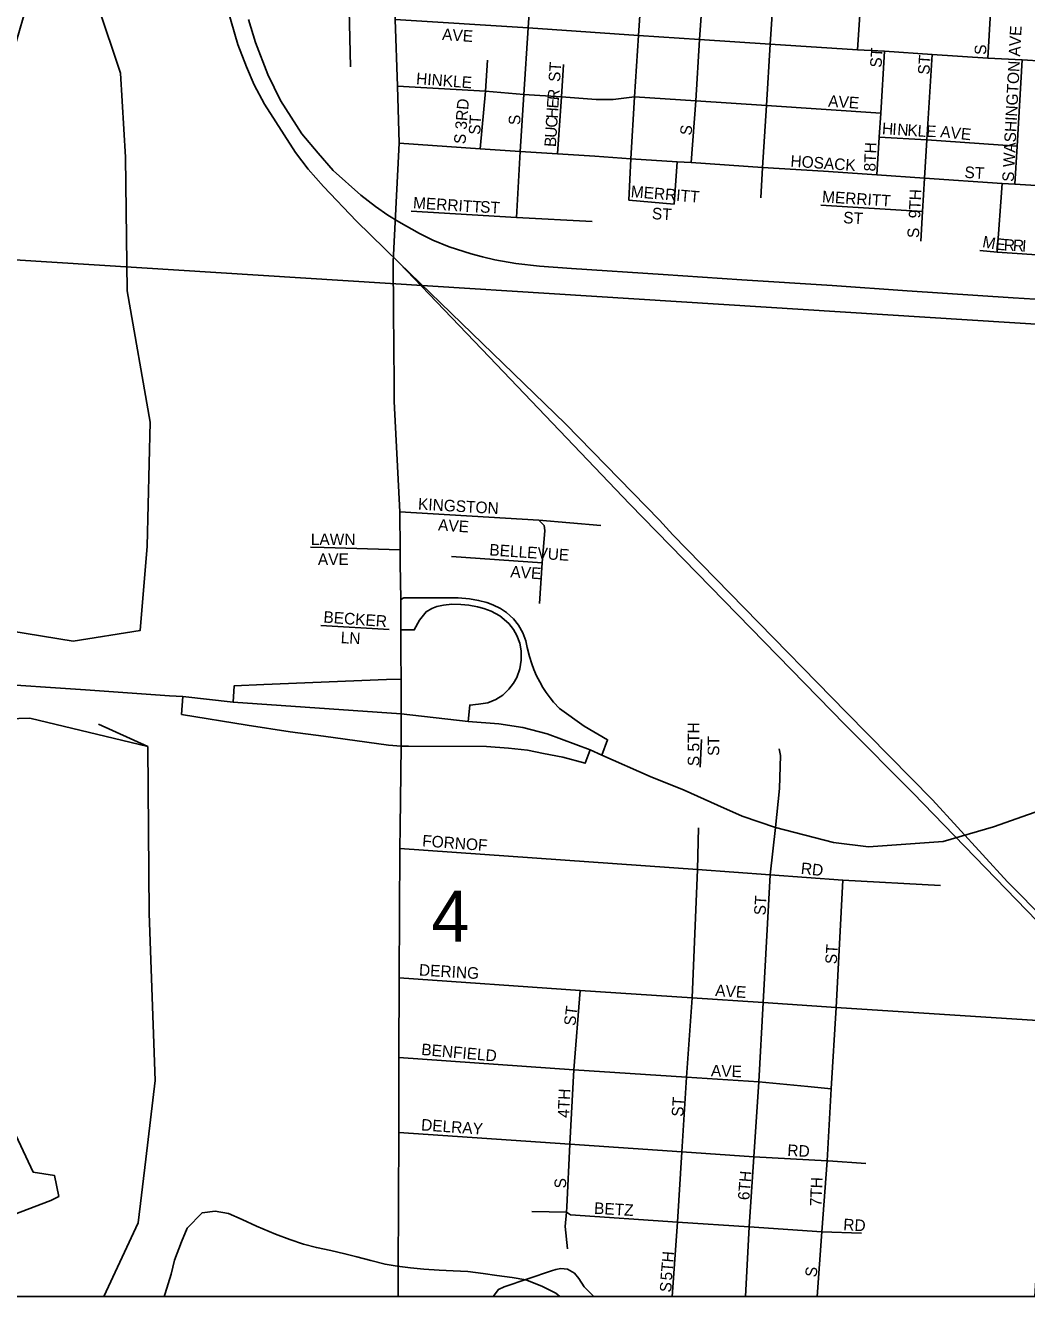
# Model space of a CAD drawing. Extents: x 0 to 34, y -6.2 to 22.
# Drawn here: x 6.622 to 7.442, y 14.39 to 15.431 of the extents above; entities that cross this region are included whole.
import ezdxf

# ---------------------------------------------------------------- set-up
doc = ezdxf.new("R2010")
doc.units = 0
for name, color, linetype in [('GM_X_City_Street', 7, 'Continuous'), ('GM_X_City_Street_Text', 7, 'Continuous'), ('GM_X_Corporation', 7, 'Continuous'), ('GM_X_Interchange_Ramps', 7, 'Continuous'), ('GM_X_Minor_Lake', 7, 'Continuous'), ('GM_X_Minor_River', 7, 'Continuous'), ('GM_X_Rail_Line', 7, 'Continuous'), ('GM_X_Section', 7, 'Continuous'), ('GM_X_Section_Text', 7, 'Continuous'), ('GM_X_State_Route', 7, 'Continuous'), ('GM_X_US_Route', 7, 'Continuous'), ('SH_Data', 7, 'Continuous')]:
    doc.layers.add(name, color=color, linetype=linetype)

msp = doc.modelspace()

# ---------------------------------------------------------------- linework, layer by layer
at = {"layer": 'GM_X_City_Street'}
for points in [[(7.0239, 15.2738), (7.0268, 15.3278), (7.0298, 15.3745), (7.0334, 15.4291), (7.038, 15.4985), (7.0424, 15.569), (7.0492, 15.6645), (7.0509, 15.6892), (7.0532, 15.7269), (7.0574, 15.7894), (7.0619, 15.8546), (7.0625, 15.8665), (7.0659, 15.9194), (7.0702, 15.9893), (7.0745, 16.0608), (7.0776, 16.1158), (7.0814, 16.1791), (7.0831, 16.2336), (7.0867, 16.2909)], [(7.2239, 15.29), (7.2254, 15.3148), (7.2286, 15.3655), (7.2316, 15.4159), (7.2363, 15.4857), (7.2414, 15.556), (7.2475, 15.6502), (7.2517, 15.7133), (7.256, 15.7754), (7.2607, 15.8406), (7.2649, 15.9058), (7.2694, 15.9759), (7.2737, 16.0484), (7.2739, 16.051)], [(6.8879, 15.3974), (6.887, 15.4324), (6.8846, 15.5297), (6.8837, 15.576), (6.8815, 15.6546), (6.8786, 15.7243), (6.8737, 15.7979), (6.8717, 15.8643), (6.8699, 15.9331)], [(7.4099, 15.4045), (7.414, 15.4747), (7.4186, 15.5449), (7.4203, 15.5774), (7.4238, 15.6382), (7.4278, 15.701), (7.4318, 15.7636), (7.4357, 15.8286), (7.4395, 15.8938)], [(7.1174, 15.3219), (7.1206, 15.3726), (7.1238, 15.4229), (7.1283, 15.4929), (7.1329, 15.5632)], [(7.1669, 15.3189), (7.1708, 15.3693), (7.1738, 15.4196), (7.1786, 15.4894), (7.1829, 15.5599)], [(7.3031, 15.4113), (7.3077, 15.4813), (7.3114, 15.5515)], [(7.5089, 15.3982), (7.4724, 15.4007), (7.4381, 15.4029), (7.4099, 15.4045), (7.3643, 15.4074), (7.3253, 15.41), (7.3031, 15.4113), (7.2316, 15.4159), (7.1738, 15.4196), (7.1238, 15.4229), (7.0334, 15.4291), (6.9246, 15.436)], [(7.3191, 15.3089), (7.321, 15.3398), (7.3222, 15.3594), (7.3253, 15.41)], [(7.3549, 15.2546), (7.3563, 15.2788), (7.358, 15.3062), (7.36, 15.3376), (7.3643, 15.4074)], [(6.9941, 15.3301), (6.9984, 15.3773), (7.0002, 15.4027)], [(7.0575, 15.326), (7.0606, 15.3726), (7.0624, 15.3992)], [(7.4319, 15.3013), (7.4338, 15.3324), (7.4381, 15.4029)], [(6.9263, 15.3814), (6.9984, 15.3773), (7.0298, 15.3745), (7.0606, 15.3726), (7.0891, 15.3705), (7.1029, 15.3704), (7.1206, 15.3726), (7.1708, 15.3693), (7.2286, 15.3655), (7.3222, 15.3594)], [(6.9278, 15.3347), (6.9941, 15.3301), (7.0268, 15.3278), (7.0575, 15.326), (7.088, 15.324), (7.1174, 15.3219), (7.1555, 15.3196), (7.1669, 15.3189), (7.2254, 15.3148), (7.2752, 15.3117), (7.3191, 15.3089), (7.358, 15.3062), (7.4217, 15.3018), (7.4319, 15.3013), (7.4669, 15.299), (7.5026, 15.2966)], [(7.321, 15.3398), (7.36, 15.3376), (7.4338, 15.3324)], [(7.1158, 15.2881), (7.1174, 15.3219)], [(7.153, 15.2847), (7.1555, 15.3196)], [(7.4174, 15.2454), (7.4217, 15.3018)], [(7.1158, 15.2881), (7.153, 15.2847)], [(7.2731, 15.284), (7.3563, 15.2788)], [(6.9375, 15.2791), (7.0239, 15.2738), (7.0857, 15.2706)], [(7.4034, 15.2468), (7.4174, 15.2454), (7.4622, 15.2425)], [(6.9282, 15.0329), (7.0421, 15.0259), (7.093, 15.0217)], [(7.0428, 14.9579), (7.0449, 14.9912), (7.0471, 15.0176), (7.0464, 15.0217), (7.0421, 15.0259)], [(6.8552, 15.0039), (6.8663, 15.0036), (6.9285, 15.0018)], [(6.9705, 14.9963), (7.0449, 14.9912)], [(6.8637, 14.9397), (6.9195, 14.9366)], [(7.1744, 14.8237), (7.1755, 14.8464)], [(7.2316, 14.7357), (7.2361, 14.7743), (7.2392, 14.8064), (7.24, 14.8332), (7.2391, 14.8387)], [(7.1514, 14.3902), (7.1557, 14.4512), (7.1594, 14.5086), (7.1631, 14.5698), (7.1676, 14.6348), (7.1722, 14.74), (7.1729, 14.774)], [(6.9283, 14.7572), (7.1722, 14.74), (7.2316, 14.7357), (7.291, 14.7312), (7.371, 14.7268)], [(7.2115, 14.3902), (7.2145, 14.4472), (7.2182, 14.5045), (7.2224, 14.566), (7.226, 14.6309), (7.2316, 14.7357)], [(7.2701, 14.3902), (7.2738, 14.4431), (7.2782, 14.5014), (7.2816, 14.5602), (7.2857, 14.6268), (7.291, 14.7312)], [(6.9277, 14.6512), (7.0759, 14.6409), (7.1676, 14.6348), (7.226, 14.6309), (7.2857, 14.6268), (7.459, 14.6158)], [(7.065, 14.4637), (7.0676, 14.5151), (7.0707, 14.5759), (7.0759, 14.6409)], [(6.9275, 14.586), (7.0707, 14.5759), (7.1631, 14.5698), (7.2224, 14.566), (7.2624, 14.5621)], [(7.2624, 14.5621), (7.2816, 14.5602)], [(6.9275, 14.5246), (7.0676, 14.5151), (7.1594, 14.5086), (7.2182, 14.5045), (7.2782, 14.5014), (7.279, 14.5014)], [(7.279, 14.5014), (7.31, 14.4991)], [(7.0365, 14.4598), (7.0648, 14.4592), (7.068, 14.4572), (7.1557, 14.4512), (7.2145, 14.4472), (7.2738, 14.4431), (7.3063, 14.4421)], [(7.0656, 14.4293), (7.0637, 14.4476), (7.0648, 14.4592), (7.065, 14.4637)], [(7.0047, 14.3902), (7.0091, 14.396), (7.0137, 14.3983), (7.0524, 14.4112), (7.0561, 14.4123), (7.0602, 14.4132), (7.0629, 14.4128), (7.0656, 14.4125), (7.0713, 14.4093), (7.0749, 14.4049), (7.0794, 14.3981), (7.0873, 14.3902)]]:
    msp.add_lwpolyline(points, dxfattribs=at)
at = {"layer": 'GM_X_Corporation'}
msp.add_lwpolyline([(5.4833, 14.3902), (9.0755, 14.3902), (9.0755, 21.1902), (4.181, 21.1902)], dxfattribs=at)
at = {"layer": 'GM_X_Interchange_Ramps'}
for points in [[(7.0937, 14.8337), (7.0984, 14.8462), (7.0794, 14.8573), (7.0592, 14.8717), (7.0543, 14.8769), (7.0514, 14.8805), (7.0482, 14.8849), (7.0454, 14.889), (7.0429, 14.8935), (7.0403, 14.8986), (7.038, 14.9037), (7.0363, 14.9083), (7.0344, 14.9143), (7.0327, 14.9217), (7.0315, 14.9271), (7.029, 14.9338), (7.0254, 14.94), (7.0214, 14.9451), (7.0158, 14.9503), (7.0108, 14.9537), (7.0045, 14.9568), (6.9995, 14.9585), (6.9928, 14.9603), (6.9853, 14.9617), (6.976, 14.9625), (6.9316, 14.9624), (6.9291, 14.9611)], [(6.9291, 14.9363), (6.9401, 14.9361), (6.9444, 14.9441), (6.9498, 14.951), (6.9544, 14.9536), (6.9587, 14.9553), (6.9642, 14.9565), (6.971, 14.9571), (6.9783, 14.957), (6.9847, 14.9564), (6.9918, 14.9551), (6.9972, 14.9536), (7.003, 14.9516), (7.0102, 14.9478), (7.0175, 14.9415), (7.0214, 14.9364), (7.0241, 14.9315), (7.0265, 14.9252), (7.0277, 14.9191), (7.0278, 14.9115), (7.0267, 14.9044), (7.0241, 14.8973), (7.0213, 14.8924), (7.0176, 14.8875), (7.0126, 14.8828), (7.0069, 14.8791), (7.0004, 14.8765), (6.9928, 14.8753), (6.9856, 14.8746), (6.9842, 14.8611)], [(6.9293, 14.8959), (6.9175, 14.8955), (6.8168, 14.8914), (6.7926, 14.8903), (6.7918, 14.8769)], [(6.7505, 14.8815), (6.7495, 14.8669), (6.8033, 14.858), (6.8386, 14.8528), (6.8658, 14.8491), (6.9191, 14.8417), (6.9295, 14.841)], [(6.9295, 14.841), (6.9353, 14.841), (6.9994, 14.8407), (7.0172, 14.8394), (7.0328, 14.8377), (7.0459, 14.835), (7.0617, 14.8318), (7.08, 14.827), (7.0841, 14.8378)]]:
    msp.add_lwpolyline(points, dxfattribs=at)
at = {"layer": 'GM_X_Minor_Lake'}
for points in [[(6.6259, 15.4584), (6.6139, 15.4167), (6.593, 15.3408), (6.5725, 15.2585), (6.5713, 15.1939), (6.5501, 15.1276), (6.5135, 15.0172), (6.5025, 14.9542), (6.5836, 14.9395), (6.6609, 14.927), (6.7156, 14.9356), (6.7213, 15.0046), (6.7237, 15.1064), (6.705, 15.2139), (6.7037, 15.3233), (6.6995, 15.392), (6.6809, 15.4476)], [(6.6253, 14.8638), (6.5532, 14.8618)], [(6.5532, 14.8618), (6.6253, 14.8638)], [(6.7219, 14.8406), (6.6253, 14.8638)], [(6.6814, 14.859), (6.7219, 14.8406), (6.723, 14.7039), (6.728, 14.5672), (6.7204, 14.5027), (6.714, 14.4507), (6.6858, 14.3902)], [(6.6858, 14.3902), (6.714, 14.4507), (6.7204, 14.5027), (6.728, 14.5672), (6.723, 14.7039), (6.7219, 14.8406)], [(6.6139, 14.5225), (6.6281, 14.492), (6.6456, 14.4893), (6.6489, 14.4722), (6.6424, 14.4688), (6.6059, 14.4549)], [(6.6059, 14.4549), (6.6424, 14.4688), (6.6489, 14.4722), (6.6456, 14.4893), (6.6281, 14.492), (6.6139, 14.5225)]]:
    msp.add_lwpolyline(points, dxfattribs=at)
at = {"layer": 'GM_X_Minor_River'}
msp.add_lwpolyline([(6.7354, 14.3902), (6.7362, 14.3926), (6.7409, 14.4085), (6.7437, 14.4199), (6.7495, 14.435), (6.7541, 14.4463), (6.7664, 14.4588), (6.777, 14.4602), (6.7879, 14.4582), (6.7993, 14.4532), (6.8109, 14.4478), (6.8264, 14.4412), (6.8381, 14.4369), (6.8494, 14.433), (6.86, 14.4303), (6.8717, 14.4279), (6.8834, 14.4252), (6.8932, 14.4228), (6.9046, 14.4197), (6.9163, 14.4166), (6.9261, 14.415), (6.9371, 14.4137), (6.948, 14.4125), (6.9605, 14.4117), (6.9719, 14.4112), (6.984, 14.4107), (6.9965, 14.4091), (7.0078, 14.4075), (7.0203, 14.4059), (7.0316, 14.4039), (7.0445, 14.3988), (7.0561, 14.393), (7.0593, 14.3902)], dxfattribs=at)
at = {"layer": 'GM_X_Rail_Line'}
for points in [[(6.9277, 15.2368), (6.8929, 15.2709), (6.8657, 15.2992), (6.8533, 15.3134), (6.8428, 15.327), (6.8175, 15.3666), (6.8091, 15.3826), (6.8027, 15.3974), (6.7955, 15.4155), (6.7871, 15.4449)], [(6.9274, 15.2702), (6.9186, 15.2759), (6.9083, 15.2829), (6.8964, 15.2923), (6.8738, 15.3125), (6.8614, 15.3266), (6.8481, 15.3425), (6.8305, 15.3698), (6.8202, 15.3911), (6.81, 15.4171), (6.8045, 15.436)], [(7.5026, 15.2037), (7.4307, 15.2081), (7.3437, 15.2139), (7.2824, 15.2183), (7.2084, 15.2228), (7.144, 15.2272), (7.069, 15.2322), (7.0427, 15.2341), (7.0233, 15.2363), (7.006, 15.2393), (6.9959, 15.2417), (6.9866, 15.2441), (6.9688, 15.2499), (6.9554, 15.2553), (6.9443, 15.2608), (6.9274, 15.2702)], [(7.6869, 14.3902), (7.6461, 14.4451), (7.6191, 14.4818), (7.5959, 14.5134), (7.5363, 14.5949), (7.5097, 14.6288), (7.4754, 14.6708), (7.45, 14.698), (7.3488, 14.8025), (7.2927, 14.8586), (7.1166, 15.0392), (7.0016, 15.1599), (6.9277, 15.2368)], [(6.9277, 15.2368), (7.064, 15.1049), (7.1411, 15.0259), (7.152, 15.014), (7.2103, 14.9543), (7.294, 14.8686), (7.3646, 14.797), (7.426, 14.7299), (7.4578, 14.698), (7.4811, 14.6739), (7.4975, 14.654), (7.5279, 14.6228), (7.5514, 14.5987), (7.5933, 14.5576), (7.6647, 14.4843), (7.6908, 14.457), (7.7165, 14.4308), (7.7565, 14.3902)]]:
    msp.add_lwpolyline(points, dxfattribs=at)
at = {"layer": 'GM_X_Section'}
msp.add_line((6.449, 14.3902), (7.4483, 14.3902), dxfattribs=at)
msp.add_lwpolyline([(7.5576, 16.2055), (7.497, 15.1834), (6.5086, 15.2458), (6.5658, 16.0353), (6.5704, 16.0443), (6.5735, 16.0466), (6.5731, 16.0496), (6.5693, 16.0527), (6.5637, 16.0565), (6.5603, 16.0599), (6.5603, 16.0637), (6.5622, 16.0671), (6.5676, 16.0735), (6.582, 16.0863), (6.5935, 16.0976), (6.6121, 16.1149), (6.632, 16.1352), (6.6415, 16.1465), (6.6507, 16.159), (6.658, 16.1722), (6.671, 16.2039), (6.6853, 16.2364), (6.6948, 16.25), (6.6949, 16.2608)], close=True, dxfattribs=at)
msp.add_lwpolyline([(7.4483, 14.3902), (7.497, 15.1834), (6.5086, 15.2458), (6.449, 14.3902)], dxfattribs=at)
at = {"layer": 'GM_X_State_Route'}
for points in [[(6.1123, 14.9543), (6.1667, 14.9471), (6.257, 14.9328), (6.3212, 14.9233), (6.3764, 14.9166), (6.3797, 14.9159), (6.4766, 14.9035), (6.5712, 14.8923), (6.5891, 14.8924), (6.6708, 14.887), (6.7397, 14.8822)], [(6.7397, 14.8822), (6.7505, 14.8815), (6.7918, 14.8769), (6.9294, 14.8673)], [(6.9294, 14.8673), (6.9842, 14.8611), (7.0094, 14.8593), (7.0291, 14.8563), (7.0489, 14.8511), (7.0841, 14.8378), (7.0937, 14.8337), (7.1333, 14.816), (7.1612, 14.805), (7.1885, 14.7926), (7.2087, 14.7837), (7.2361, 14.7743), (7.2834, 14.7621), (7.3121, 14.7585), (7.3733, 14.7628), (7.4146, 14.775), (7.4718, 14.795), (7.4933, 14.8037), (7.5295, 14.8185), (7.5554, 14.829), (7.6059, 14.8467)]]:
    msp.add_lwpolyline(points, dxfattribs=at)
at = {"layer": 'GM_X_US_Route'}
for points in [[(6.9278, 15.3347), (6.9278, 15.3347), (6.9263, 15.3814), (6.9246, 15.436), (6.922, 15.5062), (6.9201, 15.5768), (6.9178, 15.648), (6.917, 15.6734), (6.9156, 15.7255), (6.9125, 15.7988), (6.9107, 15.8651), (6.9103, 15.8775), (6.9083, 15.9307), (6.9063, 16.0007), (6.9045, 16.0558), (6.9041, 16.0718), (6.9023, 16.1227), (6.9001, 16.1907), (6.8984, 16.3024), (6.8983, 16.3122)], [(6.9232, 15.1971), (6.9228, 15.2379), (6.9278, 15.3347)], [(6.9237, 15.1381), (6.9232, 15.1971)], [(6.9287, 14.9907), (6.9285, 15.0018), (6.9282, 15.0329), (6.9238, 15.1231), (6.9237, 15.1348), (6.9237, 15.1381)], [(6.9294, 14.8673), (6.9293, 14.8959), (6.9292, 14.9172), (6.9291, 14.9363), (6.9291, 14.9611), (6.9287, 14.9907)], [(6.9295, 14.841), (6.9294, 14.8673)], [(6.9285, 14.7745), (6.9295, 14.841)], [(6.927, 14.3902), (6.9269, 14.411), (6.9275, 14.5246), (6.9275, 14.586), (6.9277, 14.6512), (6.9283, 14.7572), (6.9285, 14.7745)]]:
    msp.add_lwpolyline(points, dxfattribs=at)
at = {"layer": 'SH_Data'}
msp.add_lwpolyline([(9.0755, 21.1902), (9.0755, 14.3902), (2.2755, 14.3902), (2.2755, 21.1902)], close=True, dxfattribs=at)

# ---------------------------------------------------------------- texts
at = {"layer": 'GM_X_City_Street_Text'}
for s, rotation, p in [('AVE', 356.0569, (6.9627, 15.4193)), ('S WASHINGTON AVE', 87.0768, (7.4311, 15.3029)), ('ST', 86.4254, (7.3228, 15.3964)), ('ST', 86.4254, (7.362, 15.3906)), ('S', 90, (7.4086, 15.4071)), ('ST', 86.4254, (7.0595, 15.3847)), ('HINKLE', 355.5994, (6.9414, 15.3831)), ('R', 84.3812, (7.0585, 15.3696)), ('S 3RD', 85.3669, (6.982, 15.3337)), ('E', 86.4676, (7.0581, 15.363)), ('AVE', 356.0569, (7.2789, 15.3647)), ('ST', 86.4262, (6.9941, 15.3414)), ('S', 90, (7.027, 15.3496)), ('C', 86.4524, (7.0571, 15.3472)), ('H', 86.4346, (7.0576, 15.3547)), ('U', 86.4573, (7.0566, 15.3389)), ('S', 82.8783, (7.167, 15.3407)), ('H', 356.2165, (7.323, 15.3422)), ('I', 356.2475, (7.3314, 15.3417)), ('N', 356.2165, (7.3355, 15.3414)), ('K', 356.2251, (7.3438, 15.3409)), ('L', 356.2324, (7.3521, 15.3403)), ('E', 359.0782, (7.3593, 15.3398)), ('AVE', 354.0895, (7.3706, 15.3397)), ('B', 86.4524, (7.0561, 15.3314)), ('8TH', 87.7108, (7.3178, 15.3114)), ('HOSACK', 355.988, (7.248, 15.3156)), ('ST', 356.4254, (7.3905, 15.3064)), ('MERRITT', 355.3132, (7.1172, 15.2906)), ('MERRITT', 356.2504, (7.2739, 15.2864)), ('9TH', 87.7108, (7.3545, 15.273)), ('MERRITT', 356.2504, (6.9389, 15.2814)), ('ST', 356.4254, (6.9938, 15.2781)), ('ST', 356.4262, (7.1345, 15.2726)), ('ST', 356.4254, (7.2912, 15.2693)), ('S', 90, (7.3536, 15.2571)), ('M', 349.133, (7.4049, 15.2497)), ('E', 353.7802, (7.4156, 15.2477)), ('R', 356.5452, (7.4227, 15.2469)), ('R', 356.629, (7.4302, 15.2465)), ('I', 356.631, (7.4377, 15.246)), ('KINGSTON', 356.7741, (6.943, 15.0347)), ('AVE', 356.0494, (6.9594, 15.0176)), ('LAWN', 0, (6.8554, 15.0056)), ('BELLEVUE', 356.0298, (7.0014, 14.9972)), ('AVE', 0, (6.8612, 14.9893)), ('AVE', 356.0574, (7.0186, 14.9793)), ('BECKER', 355.8387, (6.8655, 14.9422)), ('LN', 356.989, (6.8797, 14.9253)), ('S 5TH', 90, (7.1736, 14.8246)), ('ST', 90, (7.1899, 14.833)), ('FORNOF', 355.766, (6.9464, 14.7589)), ('RD', 353.9946, (7.2564, 14.7364)), ('ST', 86.4254, (7.2278, 14.7022)), ('ST', 86.4254, (7.2861, 14.6622)), ('DERING', 356.6313, (6.9438, 14.6531)), ('AVE', 356.0569, (7.1864, 14.6364)), ('ST', 82.8783, (7.072, 14.6115)), ('BENFIELD', 354.8821, (6.9456, 14.5881)), ('AVE', 358.0186, (7.183, 14.5706)), ('4TH', 87.7108, (7.067, 14.5364)), ('ST', 86.4254, (7.1603, 14.5372)), ('DELRAY', 355.9127, (6.9455, 14.5263)), ('RD', 356.989, (7.2455, 14.5054)), ('6TH', 85.4202, (7.2145, 14.4689)), ('S', 90, (7.0645, 14.4788)), ('7TH', 87.7108, (7.2736, 14.4639)), ('BETZ', 356.7313, (7.0872, 14.458)), ('RD', 356.8222, (7.2913, 14.4446)), ('5TH', 85.4202, (7.1511, 14.4031)), ('S', 82.8817, (7.2695, 14.4057)), ('S', 82.8783, (7.1503, 14.3932))]:
    msp.add_text(s, height=0.00947, rotation=rotation, dxfattribs=at).set_placement(p)
at = {"layer": 'GM_X_Section_Text'}
msp.add_text('4', height=0.0419, rotation=0, dxfattribs=at).set_placement((6.9542, 14.6808))

doc.saveas('drawing.dxf')
